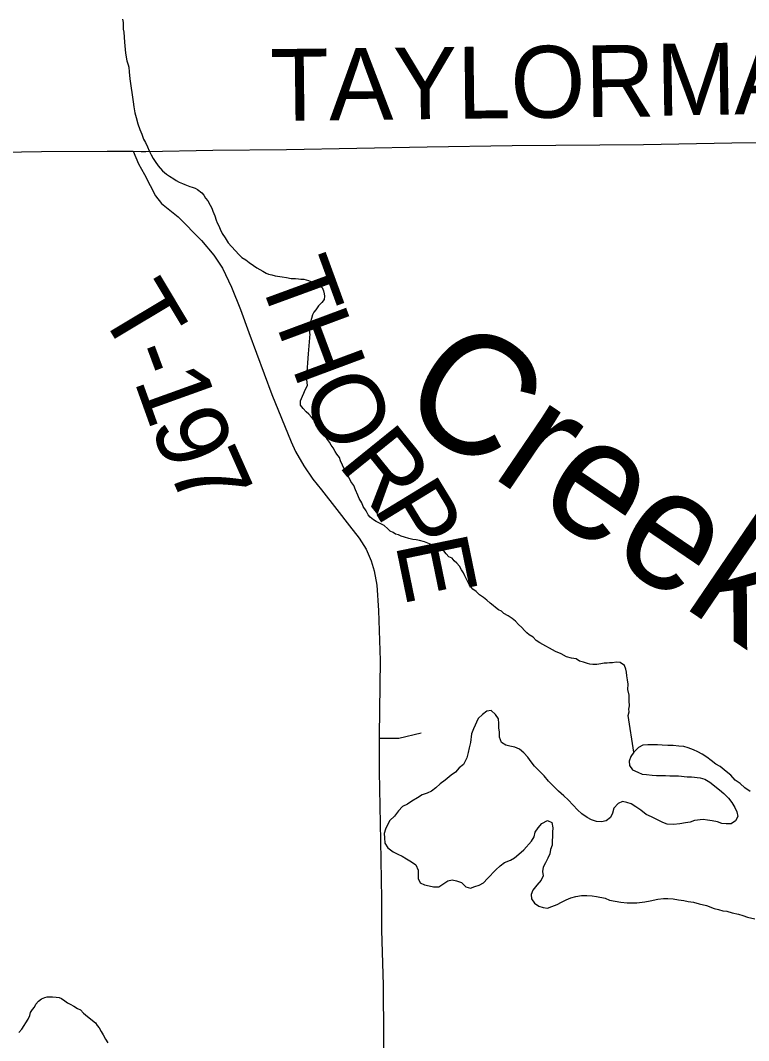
# Model space of a CAD drawing. Extents: x -10.1 to 68, y -9.5 to 29.2.
# Drawn here: x 2.607 to 3.183, y 18.175 to 18.982 of the extents above; entities that cross this region are included whole.
import ezdxf

# ---------------------------------------------------------------- set-up
doc = ezdxf.new("R2010")
doc.units = 0
for name, color, linetype in [('GM_X_Major_Lake', 7, 'Continuous'), ('GM_X_Major_River', 7, 'Continuous'), ('GM_X_Minor_River', 7, 'Continuous'), ('GM_X_Minor_River_Text', 7, 'Continuous'), ('GM_X_Township_Road', 7, 'Continuous'), ('GM_X_Township_Road_Text', 7, 'Continuous'), ('GM_X_Township_Subdivision', 7, 'Continuous')]:
    doc.layers.add(name, color=color, linetype=linetype)

msp = doc.modelspace()

# ---------------------------------------------------------------- linework, layer by layer
at = {"layer": 'GM_X_Major_Lake'}
for points in [[(3.13404, 18.38357), (3.13746, 18.38358), (3.14429, 18.38284), (3.14809, 18.38171), (3.1519, 18.37944), (3.15951, 18.37339), (3.16294, 18.37036), (3.16675, 18.36657), (3.16942, 18.36315), (3.1717, 18.35936), (3.17323, 18.35594), (3.174, 18.35215), (3.17212, 18.34872), (3.16871, 18.34643), (3.16491, 18.34641), (3.16149, 18.34678), (3.15807, 18.34791), (3.15389, 18.34866), (3.15009, 18.34941), (3.14667, 18.34978), (3.13984, 18.34899), (3.13642, 18.34784), (3.13263, 18.34707), (3.12808, 18.34629), (3.12314, 18.3459), (3.1182, 18.34626), (3.11478, 18.34739), (3.1106, 18.34966), (3.10566, 18.35192), (3.10147, 18.35381), (3.09729, 18.35722), (3.09348, 18.35987), (3.08968, 18.36214), (3.08626, 18.36326), (3.08284, 18.36401), (3.07942, 18.36248), (3.07602, 18.35867), (3.07489, 18.35486), (3.07338, 18.35144), (3.06997, 18.34877), (3.06618, 18.34799), (3.06238, 18.34836), (3.0582, 18.34949), (3.05478, 18.35138), (3.05059, 18.3544), (3.04717, 18.35744), (3.04374, 18.36122), (3.03993, 18.3654), (3.0365, 18.36843), (3.03231, 18.37221), (3.02812, 18.37638), (3.02431, 18.38017), (3.02088, 18.38434), (3.01327, 18.39192), (3.0106, 18.39533), (3.00793, 18.39913), (3.00488, 18.40254), (3.00145, 18.40557), (2.99765, 18.40708), (2.99385, 18.40782), (2.99043, 18.40857), (2.98701, 18.41084), (2.98548, 18.41502), (2.98547, 18.41882), (2.98508, 18.42224), (2.98506, 18.42566), (2.98467, 18.42946), (2.98238, 18.43288), (2.97896, 18.43591), (2.97554, 18.43552), (2.97213, 18.43284), (2.96873, 18.42979), (2.96495, 18.42142), (2.96345, 18.41761), (2.96271, 18.41076), (2.96158, 18.40658), (2.96083, 18.40277), (2.95971, 18.39859), (2.95706, 18.39326), (2.95365, 18.39059), (2.95063, 18.38715), (2.94722, 18.38486), (2.94267, 18.38104), (2.9385, 18.37799), (2.9351, 18.37494), (2.93169, 18.37227), (2.92827, 18.37074), (2.92448, 18.3692), (2.92069, 18.36691), (2.91614, 18.36423), (2.91273, 18.36194), (2.90894, 18.36003), (2.90553, 18.35659), (2.90251, 18.3524), (2.89872, 18.34897), (2.89684, 18.34554), (2.89533, 18.34212), (2.8942, 18.33869), (2.89459, 18.33527), (2.89498, 18.33109), (2.89727, 18.3273)], [(3.18381, 18.37194), (3.17963, 18.37497), (3.17582, 18.37838), (3.17202, 18.38103), (3.16859, 18.38482), (3.16478, 18.38785), (3.16021, 18.39164), (3.15679, 18.39353), (3.15299, 18.39656), (3.14956, 18.39921), (3.14576, 18.40147), (3.14233, 18.40336), (3.13891, 18.40487), (3.13473, 18.40638), (3.13131, 18.40751), (3.12751, 18.40788), (3.12295, 18.40824), (3.11878, 18.40823), (3.11422, 18.40859), (3.11042, 18.40896), (3.10283, 18.40894), (3.09903, 18.40854), (3.09562, 18.40663), (3.09183, 18.4032), (3.08956, 18.39977), (3.08806, 18.39597), (3.08845, 18.39254), (3.09074, 18.38913), (3.09492, 18.38724), (3.09834, 18.38573), (3.10176, 18.38536), (3.10631, 18.385), (3.10973, 18.38463), (3.11315, 18.38464), (3.11695, 18.38465), (3.12037, 18.38428), (3.1272, 18.38431), (3.13404, 18.38357)], [(2.89727, 18.3273), (2.90146, 18.32427), (2.90526, 18.32238), (2.90868, 18.32087), (2.91211, 18.3186), (2.91591, 18.31633), (2.91933, 18.31406), (2.92124, 18.30989), (2.92126, 18.30647), (2.92127, 18.30304), (2.9228, 18.29963), (2.92622, 18.29812), (2.93002, 18.29737), (2.93344, 18.29662), (2.93761, 18.29663), (2.9414, 18.29931), (2.94481, 18.30122), (2.94823, 18.30199), (2.95165, 18.30124), (2.95545, 18.30011), (2.95888, 18.2967), (2.96268, 18.29557), (2.96609, 18.29673), (2.9695, 18.29788), (2.97292, 18.29979), (2.97594, 18.30322), (2.98276, 18.31009), (2.98617, 18.31314), (2.98957, 18.31581), (2.99413, 18.31773), (2.99754, 18.31964), (3.00095, 18.32231), (3.00473, 18.32575), (3.01079, 18.33261), (3.01306, 18.33604), (3.0138, 18.33984), (3.01607, 18.34327), (3.0191, 18.3467), (3.02365, 18.349), (3.02707, 18.34749), (3.02784, 18.34331), (3.02747, 18.33988), (3.02748, 18.33646), (3.02711, 18.33304), (3.02713, 18.32962), (3.02599, 18.32619), (3.02525, 18.32277), (3.02374, 18.31934), (3.02185, 18.31554), (3.01996, 18.31211), (3.0196, 18.30869), (3.01998, 18.30526), (3.01847, 18.30184), (3.01507, 18.29803), (3.01204, 18.29383), (3.01054, 18.29041), (3.01093, 18.28699), (3.01321, 18.28357), (3.01664, 18.2813), (3.02006, 18.28017), (3.02348, 18.27981), (3.02689, 18.28096), (3.03106, 18.28249), (3.03448, 18.2844), (3.03827, 18.28632), (3.04206, 18.28785), (3.04585, 18.289), (3.05041, 18.28978), (3.05458, 18.28979), (3.05876, 18.28943), (3.06218, 18.28906), (3.06902, 18.28756), (3.07244, 18.28605), (3.08156, 18.28456), (3.0865, 18.28381), (3.09409, 18.28384), (3.10055, 18.28462), (3.10472, 18.28539), (3.11079, 18.28693), (3.11535, 18.28733), (3.11876, 18.28734), (3.12294, 18.28697), (3.12712, 18.28622), (3.1313, 18.28586), (3.13472, 18.28511), (3.1389, 18.28436), (3.14345, 18.28324), (3.14916, 18.28173), (3.15524, 18.27947), (3.15866, 18.27872), (3.16208, 18.27759), (3.1655, 18.27723), (3.16968, 18.2761), (3.17462, 18.27497), (3.17804, 18.27384), (3.18184, 18.27272), (3.18754, 18.27122)]]:
    msp.add_lwpolyline(points, dxfattribs=at)
at = {"layer": 'GM_X_Major_River'}
for points in [[(3.13404, 18.38357), (3.13746, 18.38358), (3.14429, 18.38284), (3.14809, 18.38171), (3.1519, 18.37944), (3.15951, 18.37339), (3.16294, 18.37036), (3.16675, 18.36657), (3.16942, 18.36315), (3.1717, 18.35936), (3.17323, 18.35594), (3.174, 18.35215), (3.17212, 18.34872), (3.16871, 18.34643), (3.16491, 18.34641), (3.16149, 18.34678), (3.15807, 18.34791), (3.15389, 18.34866), (3.15009, 18.34941), (3.14667, 18.34978), (3.13984, 18.34899), (3.13642, 18.34784), (3.13263, 18.34707), (3.12808, 18.34629), (3.12314, 18.3459), (3.1182, 18.34626), (3.11478, 18.34739), (3.1106, 18.34966), (3.10566, 18.35192), (3.10147, 18.35381), (3.09729, 18.35722), (3.09348, 18.35987), (3.08968, 18.36214), (3.08626, 18.36326), (3.08284, 18.36401), (3.07942, 18.36248), (3.07602, 18.35867), (3.07489, 18.35486), (3.07338, 18.35144), (3.06997, 18.34877), (3.06618, 18.34799), (3.06238, 18.34836), (3.0582, 18.34949), (3.05478, 18.35138), (3.05059, 18.3544), (3.04717, 18.35744), (3.04374, 18.36122), (3.03993, 18.3654), (3.0365, 18.36843), (3.03231, 18.37221), (3.02812, 18.37638), (3.02431, 18.38017), (3.02088, 18.38434), (3.01327, 18.39192), (3.0106, 18.39533), (3.00793, 18.39913), (3.00488, 18.40254), (3.00145, 18.40557), (2.99765, 18.40708), (2.99385, 18.40782), (2.99043, 18.40857), (2.98701, 18.41084), (2.98548, 18.41502), (2.98547, 18.41882), (2.98508, 18.42224), (2.98506, 18.42566), (2.98467, 18.42946), (2.98238, 18.43288), (2.97896, 18.43591), (2.97554, 18.43552), (2.97213, 18.43284), (2.96873, 18.42979), (2.96495, 18.42142), (2.96345, 18.41761), (2.96271, 18.41076), (2.96158, 18.40658), (2.96083, 18.40277), (2.95971, 18.39859), (2.95706, 18.39326), (2.95365, 18.39059), (2.95063, 18.38715), (2.94722, 18.38486), (2.94267, 18.38104), (2.9385, 18.37799), (2.9351, 18.37494), (2.93169, 18.37227), (2.92827, 18.37074), (2.92448, 18.3692), (2.92069, 18.36691), (2.91614, 18.36423), (2.91273, 18.36194), (2.90894, 18.36003), (2.90553, 18.35659), (2.90251, 18.3524), (2.89872, 18.34897), (2.89684, 18.34554), (2.89533, 18.34212), (2.8942, 18.33869), (2.89459, 18.33527), (2.89498, 18.33109), (2.89727, 18.3273)], [(3.18381, 18.37194), (3.17963, 18.37497), (3.17582, 18.37838), (3.17202, 18.38103), (3.16859, 18.38482), (3.16478, 18.38785), (3.16021, 18.39164), (3.15679, 18.39353), (3.15299, 18.39656), (3.14956, 18.39921), (3.14576, 18.40147), (3.14233, 18.40336), (3.13891, 18.40487), (3.13473, 18.40638), (3.13131, 18.40751), (3.12751, 18.40788), (3.12295, 18.40824), (3.11878, 18.40823), (3.11422, 18.40859), (3.11042, 18.40896), (3.10283, 18.40894), (3.09903, 18.40854), (3.09562, 18.40663), (3.09183, 18.4032), (3.08956, 18.39977), (3.08806, 18.39597), (3.08845, 18.39254), (3.09074, 18.38913), (3.09492, 18.38724), (3.09834, 18.38573), (3.10176, 18.38536), (3.10631, 18.385), (3.10973, 18.38463), (3.11315, 18.38464), (3.11695, 18.38465), (3.12037, 18.38428), (3.1272, 18.38431), (3.13404, 18.38357)], [(2.89727, 18.3273), (2.90146, 18.32427), (2.90526, 18.32238), (2.90868, 18.32087), (2.91211, 18.3186), (2.91591, 18.31633), (2.91933, 18.31406), (2.92124, 18.30989), (2.92126, 18.30647), (2.92127, 18.30304), (2.9228, 18.29963), (2.92622, 18.29812), (2.93002, 18.29737), (2.93344, 18.29662), (2.93761, 18.29663), (2.9414, 18.29931), (2.94481, 18.30122), (2.94823, 18.30199), (2.95165, 18.30124), (2.95545, 18.30011), (2.95888, 18.2967), (2.96268, 18.29557), (2.96609, 18.29673), (2.9695, 18.29788), (2.97292, 18.29979), (2.97594, 18.30322), (2.98276, 18.31009), (2.98617, 18.31314), (2.98957, 18.31581), (2.99413, 18.31773), (2.99754, 18.31964), (3.00095, 18.32231), (3.00473, 18.32575), (3.01079, 18.33261), (3.01306, 18.33604), (3.0138, 18.33984), (3.01607, 18.34327), (3.0191, 18.3467), (3.02365, 18.349), (3.02707, 18.34749), (3.02784, 18.34331), (3.02747, 18.33988), (3.02748, 18.33646), (3.02711, 18.33304), (3.02713, 18.32962), (3.02599, 18.32619), (3.02525, 18.32277), (3.02374, 18.31934), (3.02185, 18.31554), (3.01996, 18.31211), (3.0196, 18.30869), (3.01998, 18.30526), (3.01847, 18.30184), (3.01507, 18.29803), (3.01204, 18.29383), (3.01054, 18.29041), (3.01093, 18.28699), (3.01321, 18.28357), (3.01664, 18.2813), (3.02006, 18.28017), (3.02348, 18.27981), (3.02689, 18.28096), (3.03106, 18.28249), (3.03448, 18.2844), (3.03827, 18.28632), (3.04206, 18.28785), (3.04585, 18.289), (3.05041, 18.28978), (3.05458, 18.28979), (3.05876, 18.28943), (3.06218, 18.28906), (3.06902, 18.28756), (3.07244, 18.28605), (3.08156, 18.28456), (3.0865, 18.28381), (3.09409, 18.28384), (3.10055, 18.28462), (3.10472, 18.28539), (3.11079, 18.28693), (3.11535, 18.28733), (3.11876, 18.28734), (3.12294, 18.28697), (3.12712, 18.28622), (3.1313, 18.28586), (3.13472, 18.28511), (3.1389, 18.28436), (3.14345, 18.28324), (3.14916, 18.28173), (3.15524, 18.27947), (3.15866, 18.27872), (3.16208, 18.27759), (3.1655, 18.27723), (3.16968, 18.2761), (3.17462, 18.27497), (3.17804, 18.27384), (3.18184, 18.27272), (3.18754, 18.27122)]]:
    msp.add_lwpolyline(points, dxfattribs=at)
at = {"layer": 'GM_X_Minor_River'}
for points in [[(2.68745, 18.98269), (2.68787, 18.98004), (2.68792, 18.97737), (2.68796, 18.97471), (2.68838, 18.97244), (2.68889, 18.96446), (2.6898, 18.95573), (2.69066, 18.94966), (2.69185, 18.94664), (2.69226, 18.94474), (2.6927, 18.94095), (2.69317, 18.93563), (2.69576, 18.91742), (2.69621, 18.91325), (2.69704, 18.90869), (2.69825, 18.90491), (2.69947, 18.89999), (2.70106, 18.89545), (2.70264, 18.89168), (2.70385, 18.88789), (2.70541, 18.88526), (2.70699, 18.88186), (2.70856, 18.87846), (2.71013, 18.87545), (2.7117, 18.87243), (2.71326, 18.87017), (2.71559, 18.86679), (2.71908, 18.86266), (2.72217, 18.86005), (2.72447, 18.85857), (2.72792, 18.85634), (2.72984, 18.85523), (2.73214, 18.85375), (2.73482, 18.85265), (2.73673, 18.85193), (2.74056, 18.85047), (2.74247, 18.84974), (2.74476, 18.84901), (2.74667, 18.8479), (2.75014, 18.8453), (2.75169, 18.84342), (2.75287, 18.84116), (2.7548, 18.83891), (2.75676, 18.83552), (2.75793, 18.83326), (2.75873, 18.83099), (2.76031, 18.82721), (2.76151, 18.82381), (2.76231, 18.82154), (2.76349, 18.81928), (2.76467, 18.81664), (2.76624, 18.81324), (2.76858, 18.80986), (2.77093, 18.80571), (2.77944, 18.79672), (2.78176, 18.7941), (2.78483, 18.79225), (2.78752, 18.79039)], [(2.78752, 18.79039), (2.79098, 18.78779), (2.79367, 18.78593), (2.79596, 18.78483), (2.79827, 18.78334), (2.80095, 18.78186), (2.80286, 18.78114), (2.80553, 18.78042), (2.80821, 18.7797), (2.81353, 18.77903), (2.81696, 18.77833), (2.82077, 18.77763), (2.82419, 18.77768), (2.82648, 18.77734), (2.82838, 18.77699), (2.83066, 18.77703), (2.83256, 18.77668), (2.83448, 18.77595), (2.83639, 18.77522), (2.83868, 18.7745), (2.84251, 18.77266), (2.8452, 18.77042), (2.84638, 18.76778), (2.8468, 18.76551), (2.84721, 18.76361), (2.84688, 18.76094), (2.84502, 18.75863), (2.84241, 18.75593), (2.84018, 18.75285), (2.83869, 18.75092), (2.83758, 18.749), (2.83688, 18.74595), (2.83616, 18.74327), (2.83545, 18.74022), (2.83511, 18.73793), (2.83517, 18.73451), (2.83556, 18.73376), (2.83433, 18.71816)], [(2.83433, 18.71816), (2.83293, 18.70022)], [(2.86406, 18.62475), (2.86211, 18.62814), (2.86131, 18.63002), (2.85974, 18.63342), (2.85893, 18.63607), (2.85699, 18.6387), (2.85543, 18.64095), (2.85387, 18.64359), (2.85231, 18.64585), (2.85113, 18.64811), (2.84958, 18.65036), (2.84801, 18.653), (2.84218, 18.66089), (2.84062, 18.66352), (2.83868, 18.66577), (2.83674, 18.66802), (2.83481, 18.67027), (2.8325, 18.67214), (2.83017, 18.67476), (2.82823, 18.67739), (2.82817, 18.68081), (2.8289, 18.68272), (2.82963, 18.68464), (2.83073, 18.68694), (2.83183, 18.68961), (2.83367, 18.69307), (2.83293, 18.70022)], [(3.09183, 18.4032), (3.08728, 18.43219), (3.08799, 18.43486), (3.08795, 18.43714), (3.08829, 18.4398), (3.08823, 18.4436), (3.08815, 18.44816), (3.08694, 18.45271), (3.08725, 18.45689), (3.08681, 18.46031), (3.08638, 18.46334), (3.08595, 18.46638), (3.08553, 18.46865), (3.08434, 18.47167), (3.08089, 18.4739), (3.07784, 18.47423), (3.07481, 18.4738), (3.07253, 18.47376), (3.07063, 18.47335), (3.06836, 18.47332), (3.0657, 18.47289), (3.06267, 18.47247), (3.05925, 18.47241), (3.05696, 18.47275), (3.05506, 18.4731), (3.052, 18.47419), (3.04895, 18.4749), (3.04626, 18.47676), (3.04245, 18.47746), (3.03863, 18.47854), (3.03441, 18.48075), (3.02982, 18.48258), (3.01755, 18.4896), (3.01447, 18.49145), (3.01215, 18.49408), (3.00908, 18.49593), (3.00716, 18.49742), (3.00523, 18.49929), (3.00329, 18.50154), (3.00058, 18.50415), (2.99826, 18.50678), (2.99557, 18.50864), (2.99249, 18.51087), (2.98904, 18.51271), (2.98711, 18.51458), (2.98481, 18.51569), (2.9825, 18.51755), (2.98058, 18.51904), (2.97826, 18.5209), (2.97557, 18.52314), (2.97287, 18.52538), (2.96979, 18.52761), (2.96709, 18.53023), (2.9644, 18.53208), (2.96169, 18.53508), (2.96089, 18.53735), (2.95972, 18.53923), (2.95814, 18.54263), (2.95697, 18.54489), (2.95541, 18.54715), (2.95384, 18.55016), (2.9519, 18.55241), (2.94959, 18.55428), (2.94803, 18.55653), (2.94536, 18.55763), (2.94342, 18.55988), (2.9407, 18.56326), (2.93534, 18.56583), (2.92616, 18.56948), (2.92234, 18.57056), (2.91967, 18.5709), (2.91701, 18.57124), (2.91396, 18.57195), (2.91052, 18.57303), (2.90785, 18.57375), (2.90555, 18.57485), (2.90326, 18.57558), (2.90134, 18.57669), (2.89904, 18.57779), (2.89711, 18.57966), (2.89441, 18.58228), (2.89058, 18.58411), (2.88789, 18.58559), (2.88597, 18.5867), (2.88327, 18.58894), (2.88172, 18.59082), (2.88016, 18.59383), (2.87782, 18.59722), (2.87663, 18.60024), (2.87467, 18.60363), (2.87349, 18.60627), (2.87152, 18.61042), (2.87032, 18.61382), (2.86799, 18.61721), (2.86641, 18.6206), (2.86485, 18.62286), (2.86406, 18.62475)], [(2.6054, 18.18146), (2.60763, 18.18416), (2.60949, 18.18685), (2.61097, 18.18916), (2.61283, 18.19185), (2.61392, 18.19491), (2.61464, 18.1972), (2.61612, 18.19951), (2.61761, 18.20143), (2.61871, 18.20373), (2.62095, 18.20605), (2.6232, 18.20798), (2.62584, 18.20917), (2.62773, 18.20958), (2.62963, 18.20961), (2.63191, 18.20965), (2.63496, 18.20932), (2.63724, 18.20897), (2.63916, 18.20824), (2.64185, 18.20638), (2.64377, 18.2049), (2.64607, 18.20379), (2.64875, 18.20232), (2.65182, 18.20046), (2.65412, 18.19936), (2.65645, 18.19674), (2.65953, 18.19412), (2.66608, 18.18891), (2.66725, 18.18703), (2.6688, 18.18515), (2.67037, 18.18214), (2.67193, 18.1795), (2.67389, 18.17611), (2.67584, 18.1731)]]:
    msp.add_lwpolyline(points, dxfattribs=at)
at = {"layer": 'GM_X_Township_Road'}
for points in [[(2.70585, 18.87803), (2.75867, 18.87913), (2.81708, 18.87964), (2.92838, 18.88171), (2.99556, 18.8828), (3.0994, 18.88346), (3.16942, 18.88477), (3.21675, 18.88542), (3.27063, 18.88673), (3.31491, 18.8876), (3.35723, 18.88826), (3.40391, 18.88957), (3.42659, 18.89022), (3.45561, 18.89088), (3.49094, 18.89131)], [(2.14704, 18.87418), (2.19602, 18.87408), (2.28335, 18.87431), (2.35958, 18.87455), (2.42206, 18.87479), (2.49685, 18.876), (2.62326, 18.87817), (2.67513, 18.87841), (2.69588, 18.87841), (2.70206, 18.87795), (2.70585, 18.87803)], [(2.69588, 18.87841), (2.69998, 18.86828), (2.7048, 18.85984), (2.70915, 18.85115), (2.71349, 18.84295), (2.71831, 18.83692), (2.73134, 18.8263), (2.74992, 18.80773), (2.75952, 18.79617), (2.76656, 18.78577), (2.77356, 18.77082), (2.7808, 18.75321), (2.78731, 18.73487), (2.8054, 18.6859), (2.82067, 18.64837), (2.82428, 18.64081), (2.83073, 18.62945), (2.83797, 18.61907), (2.8447, 18.61038), (2.85682, 18.59504), (2.86692, 18.58216), (2.87464, 18.57227), (2.88019, 18.56359), (2.88405, 18.55442), (2.88648, 18.54649), (2.88839, 18.53512), (2.88984, 18.5151), (2.89104, 18.47553), (2.89047, 18.41624), (2.89047, 18.41426), (2.89047, 18.38767), (2.89153, 18.33296), (2.89225, 18.28712), (2.89225, 18.26227), (2.89346, 18.21885), (2.89418, 18.13634)]]:
    msp.add_lwpolyline(points, dxfattribs=at)
at = {"layer": 'GM_X_Township_Subdivision'}
msp.add_lwpolyline([(2.89047, 18.41426), (2.906, 18.41426), (2.92347, 18.41832)], dxfattribs=at)

# ---------------------------------------------------------------- texts
at = {"layer": 'GM_X_Minor_River_Text'}
msp.add_text('Creek', height=0.094754, rotation=325.79796, dxfattribs=at).set_placement((2.90178, 18.67365))
at = {"layer": 'GM_X_Township_Road_Text'}
for s, height, rotation, p in [('TAYLOR', 0.056818, 0.67938, (2.80458, 18.90216)), ('M', 0.05682, 0.89204, (3.1097, 18.90633)), ('A', 0.05682, 0.88886, (3.17136, 18.90729)), ('T', 0.05682, 290.08856, (2.79409, 18.78076)), ('T', 0.05682, 300.87189, (2.66752, 18.75286)), ('H', 0.05682, 290.43227, (2.80882, 18.7405)), ('-', 0.05682, 290.35323, (2.68813, 18.71886)), ('1', 0.05682, 289.75815, (2.6962, 18.69713)), ('O', 0.05682, 294.33991, (2.82788, 18.68974)), ('9', 0.05682, 291.73029, (2.70878, 18.6622)), ('R', 0.05682, 308.93954, (2.85677, 18.63076)), ('7', 0.05682, 294.05372, (2.72272, 18.62737)), ('P', 0.05682, 301.39646, (2.88496, 18.59607)), ('E', 0.05682, 281.64697, (2.90304, 18.56815))]:
    msp.add_text(s, height=height, rotation=rotation, dxfattribs=at).set_placement(p)

doc.saveas('drawing.dxf')
